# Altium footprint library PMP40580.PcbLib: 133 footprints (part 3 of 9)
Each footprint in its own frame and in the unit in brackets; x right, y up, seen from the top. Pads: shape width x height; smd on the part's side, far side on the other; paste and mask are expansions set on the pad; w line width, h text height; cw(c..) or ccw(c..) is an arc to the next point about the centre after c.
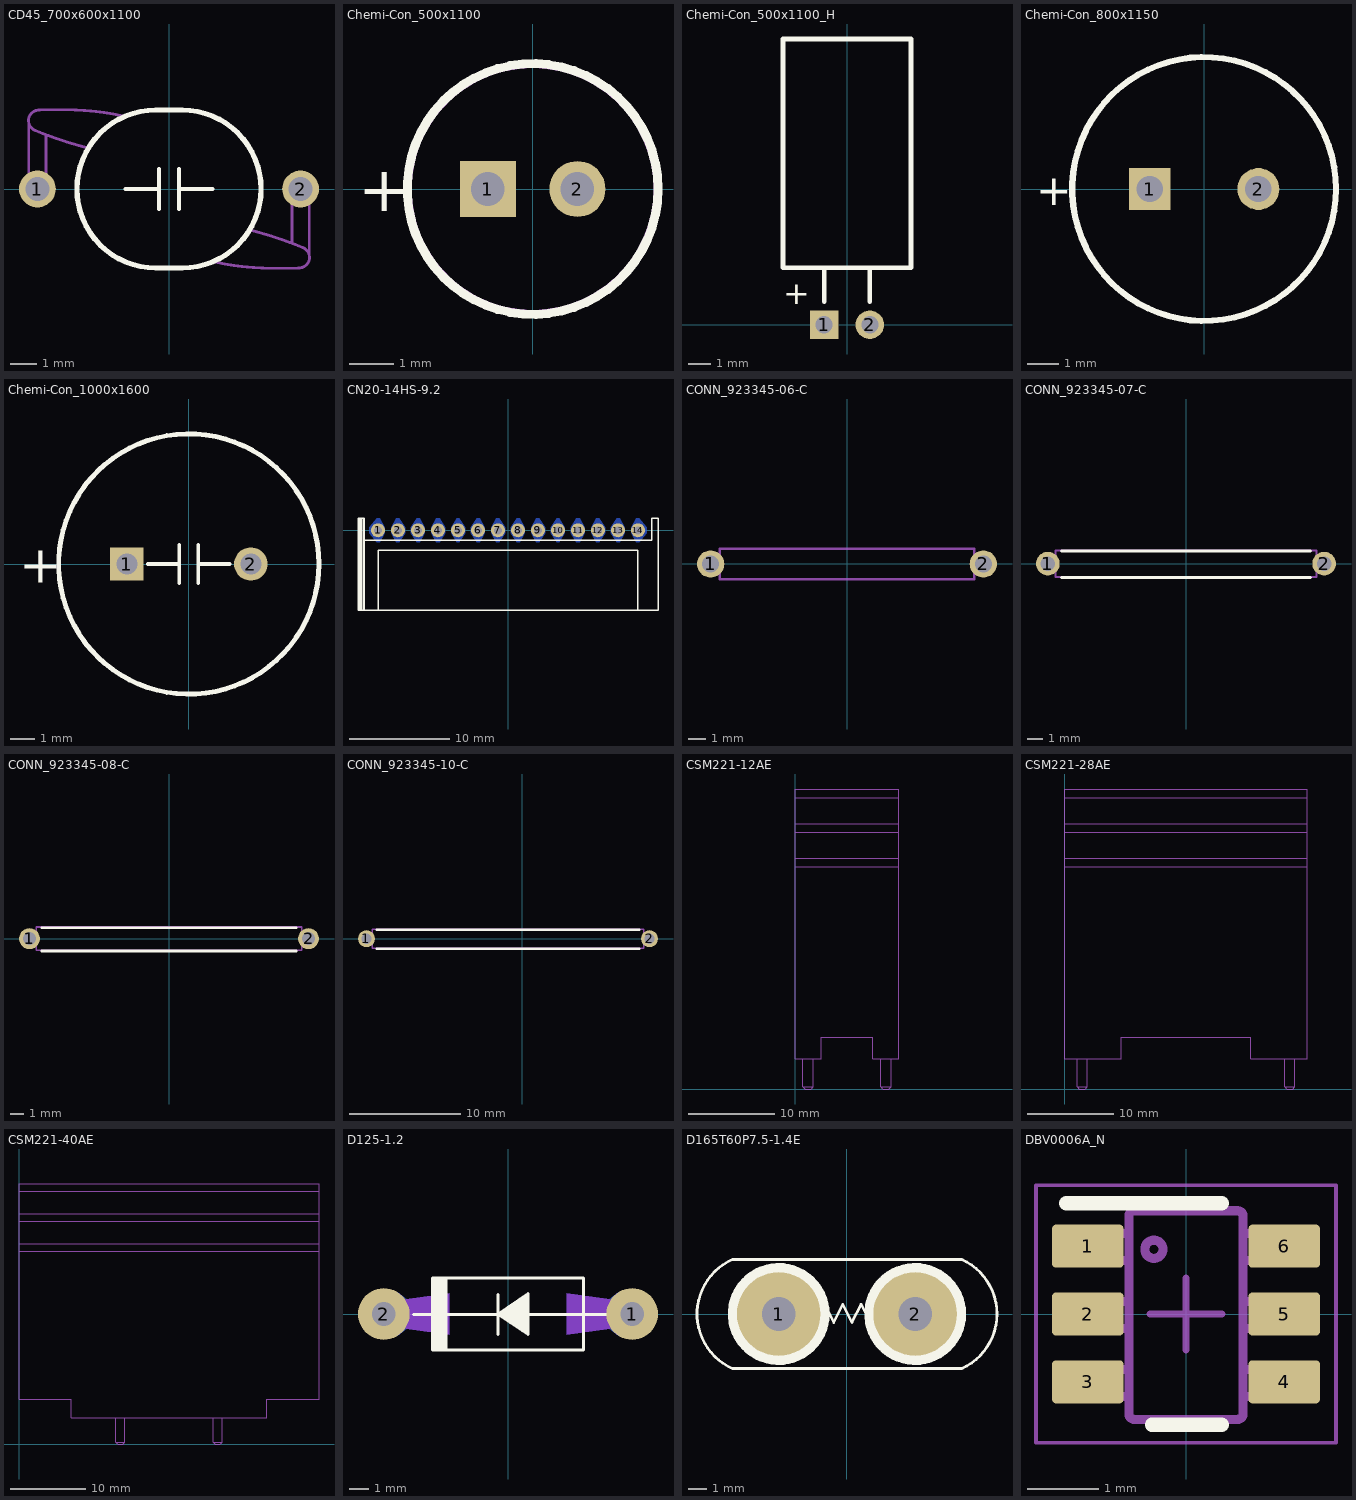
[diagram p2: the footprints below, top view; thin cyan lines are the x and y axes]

## CD45_700x600x1100 [mm] "TH, 2-Leads, Dia 7mm, Pin Spacing 10 mm"
height 11
pads (2):
  round 1.4 hole 0.9: 1(-5,0) 2(5,0)
Top Overlay:
  lines w0.15: -1.651,0 -0.381,0 ; -0.381,-0.762 -0.381,0.762 ; 0.381,-0.762 0.381,0.762 ; 0.381,0 1.651,0
  lines w0.2: -0.5,-3 cw(c-0.5,0) -0.5,3 0.5,3 cw(c0.5,0) 0.5,-3 -0.5,-3
Bottom Overlay:
  lines w0.15: -1.651,0 -0.381,0 ; -0.381,-0.762 -0.381,0.762 ; 0.381,-0.762 0.381,0.762 ; 0.381,0 1.651,0
Mechanical 5:
  drawing of 576 lines, arcs and shapes, not listed
  text ".Designator" at -2,-0.7 h1.85
3D body "CD45-102-N.stp": height 11, standoff -5, extent -5.34,-3.016 5.341,3.016

## Chemi-Con_500x1100 [mm] "TH, 2-Leads, Dia 5mm, Lead Sapcing 2mm"
height 12.5
pads (2):
  rect 1.25x1.25 hole 0.75: 1(-1,0)
  round 1.25 hole 0.75: 2(1,0)
Top Overlay:
  circle w0.2: c0,0 r2.8
  text "+" at -3.9,-0.5 h1.02
Mechanical 5:
  circle w0.1: c0,0 r2.75
  text ".Designator" at -1.524,-0.508 h1.02
  text "+" at -3.9,-0.5 h1.02
3D body "KZE_500x1100.stp": height 12.5, standoff -4.5, extent -2.75,-2.748 2.749,2.748

## Chemi-Con_500x1100_H [mm] "TH, 2-Leads, Dia 5mm, Lead Sapcing 2mm"
height 12.5
pads (2):
  rect 1.25x1.25 hole 0.75: 1(-1,0)
  round 1.25 hole 0.75: 2(1,0)
Top Overlay:
  lines w0.2: -1,1 -1,2.5 ; 1,1 1,2.5 ; -2.8,2.5 -2.8,12.5 2.8,12.5 2.8,2.5 -2.8,2.5
  text "+" at -2.8,0.9 h1.02
Mechanical 5:
  lines w0.15: -1,1 -1,2.5 ; 1,1 1,2.5 ; -2.8,2.5 2.8,2.5 2.8,12.5 -2.8,12.5 -2.8,2.5
  text "+" at -2.8,0.9 h1.02
  text ".Designator" at -1.524,-0.508 h1.02

## Chemi-Con_800x1150 [mm] "TH, 2-Leads, Dia 8mm"
height 13
pads (2):
  rect 1.35x1.35 hole 0.85: 1(-1.75,0)
  round 1.35 hole 0.85: 2(1.75,0)
Top Overlay:
  circle w0.2: c0,0 r4.25
  text "+" at -5.416,-0.527 h1
  text "+" at -5.416,-0.527 h1
Mechanical 5:
  circle w0.1: c0,0 r4.25
  text "+" at -5.416,-0.527 h1
  text "+" at -5.416,-0.527 h1
  text ".Designator" at -1.6,-0.4 h1.02
3D body: height 0, standoff -2.5, extent -2.047,-0.299 -1.45,0.3
3D body: height 0, standoff -2, extent 1.453,-0.299 2.05,0.3
3D body "KZN_800x1150.stp": height 13.01, standoff -4, extent -4.217,-4.243 4.244,4.243

## Chemi-Con_1000x1600 [mm] "TH, 2-Leads, Dia 10mm, Pin Spacing 5mm"
height 17.5
pads (2):
  rect 1.35x1.35 hole 0.85: 1(-2.5,0)
  round 1.35 hole 0.85: 2(2.5,0)
Top Overlay:
  circle w0.2: c0,0 r5.25
  lines w0.15: -1.651,0 -0.381,0 ; -0.381,-0.762 -0.381,0.762 ; 0.381,-0.762 0.381,0.762 ; 0.381,0 1.651,0
  text "+" at -6.85,-0.75 h1.5
Bottom Overlay:
  lines w0.15: -1.651,0 -0.381,0 ; -0.381,-0.762 -0.381,0.762 ; 0.381,-0.762 0.381,0.762 ; 0.381,0 1.651,0
Mechanical 5:
  circle w0.1: c0,0 r5.25
  text "+" at -6.85,-0.75 h1.5
  text ".Designator" at -1.524,-0.508 h1.02
3D body "KZN_1000x1600.stp": height 17.5, standoff -4.5, extent -5.25,-5.248 5.26,5.248

## CN20-14HS-9.2 [mm]
pads (14):
  round 1.4 / inner round 1.6 / far side round 1.4 hole 0.8: 1(-13,0) 2(-11,0) 3(-9,0) 4(-7,0) 5(-5,0) 6(-3,0) 7(-1,0) 8(1,0) 9(3,0) 10(5,0) 11(7,0) 12(9,0) 13(11,0) 14(13,0)
Bottom Layer:
  region: 13.15,-1.2 13.9,-0.3 13.9,0.3 13.15,1.2 12.85,1.2 12.3,0.3 12.3,-0.3 12.85,-1.2
  region: 11.7,0.3 11.7,-0.3 11.15,-1.2 10.85,-1.2 10.3,-0.3 10.3,0.3 10.85,1.2 11.15,1.2
  region: 9.7,0.3 9.7,-0.3 9.15,-1.2 8.85,-1.2 8.3,-0.3 8.3,0.3 8.85,1.2 9.15,1.2
  region: 7.7,0.3 7.7,-0.3 7.15,-1.2 6.85,-1.2 6.3,-0.3 6.3,0.3 6.85,1.2 7.15,1.2
  region: 5.7,0.3 5.7,-0.3 5.15,-1.2 4.85,-1.2 4.3,-0.3 4.3,0.3 4.85,1.2 5.15,1.2
  region: 3.7,0.3 3.7,-0.3 3.15,-1.2 2.85,-1.2 2.3,-0.3 2.3,0.3 2.85,1.2 3.15,1.2
  region: 1.7,0.3 1.7,-0.3 1.15,-1.2 0.85,-1.2 0.3,-0.3 0.3,0.3 0.85,1.2 1.15,1.2
  region: -0.3,0.3 -0.3,-0.3 -0.85,-1.2 -1.15,-1.2 -1.7,-0.3 -1.7,0.3 -1.15,1.2 -0.85,1.2
  region: -2.3,0.3 -2.3,-0.3 -2.85,-1.2 -3.15,-1.2 -3.7,-0.3 -3.7,0.3 -3.15,1.2 -2.85,1.2
  region: -4.3,0.3 -4.3,-0.3 -4.85,-1.2 -5.15,-1.2 -5.7,-0.3 -5.7,0.3 -5.15,1.2 -4.85,1.2
  region: -6.3,0.3 -6.3,-0.3 -6.85,-1.2 -7.15,-1.2 -7.7,-0.3 -7.7,0.3 -7.15,1.2 -6.85,1.2
  region: -8.3,0.3 -8.3,-0.3 -8.85,-1.2 -9.15,-1.2 -9.7,-0.3 -9.7,0.3 -9.15,1.2 -8.85,1.2
  region: -10.3,0.3 -10.3,-0.3 -10.85,-1.2 -11.15,-1.2 -11.7,-0.3 -11.7,0.3 -11.15,1.2 -10.85,1.2
  region: -13.15,1.2 -13.9,0.3 -13.9,-0.3 -13.15,-1.2 -12.85,-1.2 -12.3,-0.3 -12.3,0.3 -12.85,1.2
Top Overlay:
  lines w0.15: -14.95,-8 -14.95,1.2 ; -14.8,-8 -14.8,1.2 ; -14.65,-8 -14.65,1.2 ; -14.5,-8 -14.5,1.2 ; -14.4,-8 -14.4,1.2 ; -13,-8 -13,-2 13,-2 13,-8 ; -14.4,1.2 -15,1.2 -15,-8 15,-8 15,1.2 14.4,1.2 14.4,-1 -14.4,-1 -14.4,1.2 ; -14.45,-8 -14.45,1.2 -14.45,-8
Bottom Overlay:
  lines w0.5: -12,-1.25 -12,1.25 ; -10,-1.25 -10,1.25 ; -8,-1.25 -8,1.25 ; -6,-1.25 -6,1.25 ; -4,-1.25 -4,1.25 ; -2,-1.25 -2,1.25 ; 0,-1.25 0,1.25 ; 2,-1.25 2,1.25 ; 4,-1.25 4,1.25 ; 6,-1.25 6,1.25 ; 8,-1.25 8,1.25 ; 10,-1.25 10,1.25 ; 12,-1.25 12,1.25

## CONN_923345-06-C [mil] "3M, Wire jumper, 600 mil lenght, Blue"
height 255.91
pads (2):
  round 60 hole 37: 1(-300,0) 2(300,0)
Mechanical 5:
  lines w5: -281.1,-12.7 -300.79,-12.7 cw(c-300.79,0) -313.49,0 cw(c-300.79,0) -300.79,12.7 -281.1,12.7 ; -280.31,-33.46 280.31,-33.46 ; -280.31,33.46 280.31,33.46 ; -280.12,-33.46 -280.12,33.46 ; 280.12,-33.46 280.12,33.46 ; 280.12,-12.7 299.8,-12.7 ccw(c299.8,0) 312.5,0 ccw(c299.8,0) 299.8,12.7 280.12,12.7
  text ".Designator" at -55,-15 h30
3D body: height 69.93, standoff 0.07, extent -280,-34.86 280,34.86
3D body: height 35, standoff -100, extent -313.39,-13.47 -286.49,13.48
3D body: height 35, standoff -100, extent 286.61,-13.47 313.5,13.48
3D body: height 48.47, standoff 21.53, extent -300,-13.45 -250,13.44
3D body: height 48.47, standoff 21.53, extent 250,-13.39 300,13.5
3D body: height 48.5, standoff 21.5, extent -313.36,-13.44 -286.5,13.45
3D body: height 48.5, standoff 21.5, extent 286.64,-13.44 313.5,13.45

## CONN_923345-07-C [mil] "3M, Wire jumper, 700 mil lenght, Violet"
height 255.91
pads (2):
  round 60 hole 37: 1(-350,0) 2(350,0)
Top Overlay:
  lines w7.87: -314.96,-35.43 314.96,-35.43 ; -314.96,31.5 314.96,31.5
Mechanical 5:
  lines w5: -330.31,-12.7 -350,-12.7 cw(c-350,0) -362.7,0 cw(c-350,0) -350,12.7 -330.31,12.7 ; 330.31,-12.7 350,-12.7 ccw(c350,0) 362.7,0 ccw(c350,0) 350,12.7 330.31,12.7 ; -330.31,-33.46 330.31,-33.46 330.31,33.46 -330.31,33.46 -330.31,-33.46
  text ".Designator" at -55.12,-15.75 h30
3D body "923345-07-c.stp": height 73.65, standoff -196.85, extent -362.69,-33.39 362.71,33.4

## CONN_923345-08-C [mil] "3M, Wire jumper, 700 mil lenght, Violet"
height 255.91
pads (2):
  round 60 hole 37: 1(-400,0) 2(400,0)
Top Overlay:
  lines w7.87: -364.96,-35.43 364.96,-35.43 ; -364.96,31.5 364.96,31.5
Mechanical 5:
  lines w5: -380.31,-12.7 -400,-12.7 cw(c-400,0) -412.7,0 cw(c-400,0) -400,12.7 -380.31,12.7 ; 380.31,-12.7 400,-12.7 ccw(c400,0) 412.7,0 ccw(c400,0) 400,12.7 380.31,12.7 ; -380.31,-33.46 380.31,-33.46 380.31,33.46 -380.31,33.46 -380.31,-33.46
  text ".Designator" at -155.12,-15.75 h30

## CONN_923345-10-C [mil] "3M, Wire jumper, 700 mil lenght, Violet"
height 255.91
pads (2):
  round 60 hole 37: 1(-550,0) 2(450,0)
Top Overlay:
  lines w7.87: -514.96,-35.43 414.96,-35.43 ; -514.96,31.5 414.96,31.5
Mechanical 5:
  lines w5: -530.32,-12.7 -550,-12.7 cw(c-550,0) -562.7,0 cw(c-550,0) -550,12.7 -530.32,12.7 ; 430.31,-12.7 450,-12.7 ccw(c450,0) 462.7,0 ccw(c450,0) 450,12.7 430.31,12.7 ; -530.32,-33.46 430.31,-33.46 430.31,33.46 -530.32,33.46 -530.32,-33.46
  text ".Designator" at -155.12,-15.75 h30

## CSM221-12AE [mm]
Mechanical 1:
  lines w0.127: 0,25.7 12,25.7 ; 0,26.7 12,26.7 ; 0,29.7 12,29.7 ; 0,30.7 12,30.7 ; 0,33.7 12,33.7 ; 0.9,3.5 0.9,0.25 ; 2.1,3.5 2.1,0.25 ; 9.9,3.5 9.9,0.25 ; 11.1,3.5 11.1,0.25 ; 0.9,0.25 2.1,0.25 ; 0.9,0.25 1.15,0 1.85,0 2.1,0.25 ; 9.9,0.25 11.1,0.25 ; 9.9,0.25 10.15,0 10.85,0 11.1,0.25 ; 0,3.5 3,3.5 3,6 9,6 9,3.5 12,3.5 12,34.7 0,34.7 0,3.5
3D body "CSM221-12AE.stp": height 12.5, standoff 0, extent 0,0 12,34.7

## CSM221-28AE [mm]
Mechanical 1:
  lines w0.127: 0,25.7 28,25.7 ; 0,26.7 28,26.7 ; 0,29.7 28,29.7 ; 0,30.7 28,30.7 ; 0,33.7 28,33.7 ; 1.4,3.5 1.4,0.25 ; 2.6,3.5 2.6,0.25 ; 25.4,3.5 25.4,0.25 ; 26.6,3.5 26.6,0.25 ; 1.4,0.25 1.65,0 2.35,0 2.6,0.25 ; 1.4,0.25 2.6,0.25 ; 25.4,0.25 26.6,0.25 ; 25.4,0.25 25.65,0 26.35,0 26.6,0.25 ; 0,3.5 0,34.7 28,34.7 28,3.5 21.5,3.5 21.5,6 6.5,6 6.5,3.5 0,3.5
3D body "CSM221-28AE.stp": height 12.5, standoff 0, extent 0,0 28,34.7

## CSM221-40AE [mm]
Mechanical 1:
  lines w0.127: 0,25.7 40,25.7 ; 0,26.7 40,26.7 ; 0,29.7 40,29.7 ; 0,30.7 40,30.7 ; 0,33.7 40,33.7 ; 12.9,3.5 12.9,0.25 ; 14.1,3.5 14.1,0.25 ; 25.9,3.5 25.9,0.25 ; 27.1,3.5 27.1,0.25 ; 12.9,0.25 14.1,0.25 ; 12.9,0.25 13.15,0 13.85,0 14.1,0.25 ; 25.9,0.25 27.1,0.25 ; 25.9,0.25 26.15,0 26.85,0 27.1,0.25 ; 0,6 0,34.7 40,34.7 40,6 33,6 33,3.5 7,3.5 7,6 0,6
3D body "CSM221-40AE.stp": height 12.5, standoff 0, extent 0,0 40,34.7

## D125-1.2 [mm]
pads (2):
  round 2.6 / inner round 2.2 / far side round 2.6 hole 1.2: 1(6.25,0) 2(-6.25,0)
Bottom Layer:
  region: -4.45,0 -4.45,0.099 -4.526,0.283 -4.667,0.424 -4.851,0.5 -4.95,0.5 -5.049,0.5 -5.233,0.424 -5.374,0.283 -5.45,0.099 -5.45,0 -5.45,-0.099 -5.374,-0.283 -5.233,-0.424 -5.049,-0.5 -4.95,-0.5 -4.851,-0.5 -4.667,-0.424 -4.526,-0.283 -4.45,-0.099
  region: 5.45,0 5.45,0.099 5.374,0.283 5.233,0.424 5.049,0.5 4.95,0.5 4.851,0.5 4.667,0.424 4.526,0.283 4.45,0.099 4.45,0 4.45,-0.099 4.526,-0.283 4.667,-0.424 4.851,-0.5 4.95,-0.5 5.049,-0.5 5.233,-0.424 5.374,-0.283 5.45,-0.099
  region: -4.65,0.4 -5.55,1.1 -6.25,1.1 -6.25,-1.1 -5.55,-1.1 -4.65,-0.4
  region: 4.65,-0.4 5.55,-1.1 6.25,-1.1 6.25,1.1 5.55,1.1 4.65,0.4
Bottom Layer keep-out:
  region: 6.25,0.6 2.95,0.6 2.95,-0.6 6.25,-0.612 6.484,-0.565 6.683,-0.433 6.815,-0.234 6.862,0 6.815,0.234 6.683,0.433 6.484,0.565 6.25,0.612
  region: 2.95,1.05 2.95,-1.05 6.25,-0.6 6.25,0.6
  region: -6.25,-0.6 -2.95,-0.6 -2.95,0.6 -6.25,0.612 -6.484,0.565 -6.683,0.433 -6.815,0.234 -6.862,0 -6.815,-0.234 -6.683,-0.433 -6.484,-0.565 -6.25,-0.612
  region: -2.95,-1.05 -2.95,1.05 -6.25,0.6 -6.25,-0.6
Top Overlay:
  circle w1: c-6.25,0 r0.5
  lines w0.15: -4.75,-0.02 5.25,-0.02 ; -3.75,-1.75 -3.75,1.75 ; -3.625,-1.75 -3.625,1.75 ; -3.5,-1.75 -3.5,1.75 ; -3.375,-1.75 -3.375,1.75 ; -3.25,-1.75 -3.25,1.75 ; -3.125,-1.75 -3.125,1.75 ; -0.5,-1.02 -0.5,0.98 ; -0.2,-0.12 -0.2,0.08 ; -0.1,-0.22 -0.1,0.18 ; 0,-0.32 0,0.28 ; 0.1,-0.42 0.1,0.28 ; 0.2,-0.42 0.2,0.38 ; 0.3,-0.52 0.3,0.48 ; 0.4,-0.52 0.4,0.48 ; 0.5,-0.62 0.5,0.58 ; 0.6,-0.72 0.6,0.68 ; 0.7,-0.82 0.7,0.78 ; 0.8,-0.82 0.8,0.88 ; 0.9,-0.92 0.9,0.88 ; -3.8,-1.8 -3.8,1.8 3.8,1.8 3.8,-1.8 -3.8,-1.8 ; -0.5,-0.02 1,-1.02 1,1.02 -0.5,-0.02

## D165T60P7.5-1.4E [mm]
pads (2):
  round 4.6 hole 1.85: 1(-3.75,0) 2(3.75,0)
Top Overlay:
  circle w1: c-3.75,0 r2.3
  circle w1: c3.75,0 r2.3
  lines w0.15: -1.975,0.034 -1.475,0.034 -1.225,0.534 -0.725,-0.466 -0.225,0.534 0.275,-0.466 0.775,0.534 1.275,-0.466 1.525,0.034 2.025,0.034 ; -6.27,-3 cw(c-4.972,0) -6.27,3 6.31,3 cw(c4.962,0) 6.31,-3 -6.27,-3

## DBV0006A_N [mm] "SOT23, 6-Leads, Body 2.9x1.6mm, Pitch 0.95mm, Lead Span 2.8mm, IPC Medium Density"
height 1.45
pads (6):
  rrect17% 1x0.6 smd: 1(-1.375,0.95) 2(-1.375,0) 3(-1.375,-0.95) 4(1.375,-0.95) 5(1.375,0) 6(1.375,0.95)
Top Overlay:
  lines w0.2: -1.675,1.55 0.5,1.55 ; -0.475,-1.55 0.5,-1.55
Mechanical 5:
  lines w0.127: 0.724,-1.475 ccw(c0.723,-1.399) 0.8,-1.399 0.8,1.37 ccw(c0.723,1.37) 0.724,1.446 ; 0.723,-1.475 0.724,-1.475 ; 0.723,-1.475 -0.724,-1.475 -0.725,-1.475 cw(c-0.724,-1.399) -0.801,-1.399 -0.801,1.37 cw(c-0.724,1.37) -0.725,1.446 -0.724,1.446 0.723,1.446 ; 0.723,1.446 0.724,1.446 ; -1.423,-1.154 -1.206,-1.154 -1.113,-1.154 -1.081,-1.154 -0.828,-1.154 -0.801,-1.154 -0.801,-0.78 -0.828,-0.78 -1.081,-0.78 -1.113,-0.78 -1.206,-0.78 -1.423,-0.78 -1.423,-1.154 ; -1.423,-0.202 -1.206,-0.202 -1.113,-0.202 -1.081,-0.202 -0.828,-0.202 -0.801,-0.202 -0.801,0.173 -0.828,0.173 -1.081,0.173 -1.113,0.173 -1.206,0.173 -1.423,0.173 -1.423,-0.202 ; -1.423,0.751 -1.206,0.751 -1.113,0.751 -1.081,0.751 -0.828,0.751 -0.801,0.751 -0.801,1.125 -0.828,1.125 -1.081,1.125 -1.113,1.125 -1.206,1.125 -1.423,1.125 -1.423,0.751 ; -0.577,0.906 cw(c-0.45,0.906) -0.323,0.906 cw(c-0.45,0.906) -0.577,0.906 ; 0.8,-1.154 0.827,-1.154 1.08,-1.154 1.112,-1.154 1.205,-1.154 1.422,-1.154 1.422,-0.78 1.205,-0.78 1.112,-0.78 1.08,-0.78 0.827,-0.78 0.8,-0.78 0.8,-1.154 ; 0.8,-0.202 0.827,-0.202 1.08,-0.202 1.112,-0.202 1.205,-0.202 1.422,-0.202 1.422,0.173 1.205,0.173 1.112,0.173 1.08,0.173 0.827,0.173 0.8,0.173 0.8,-0.202 ; 0.8,0.751 0.827,0.751 1.08,0.751 1.112,0.751 1.205,0.751 1.422,0.751 1.422,1.125 1.205,1.125 1.112,1.125 1.08,1.125 0.827,1.125 0.8,1.125 0.8,0.751
  text ".Designator" at -0.075,0.925 h0.51
Mechanical 15:
  lines w0.05: -2.1,-1.8 2.1,-1.8 2.1,1.8 -2.1,1.8 -2.1,-1.8
  lines w0.1: -0.5,0 0.5,0 ; 0,-0.5 0,0.5
3D body "DBV0006A.stp": height 1.12, standoff 0, extent -1.422,-1.461 1.423,1.46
